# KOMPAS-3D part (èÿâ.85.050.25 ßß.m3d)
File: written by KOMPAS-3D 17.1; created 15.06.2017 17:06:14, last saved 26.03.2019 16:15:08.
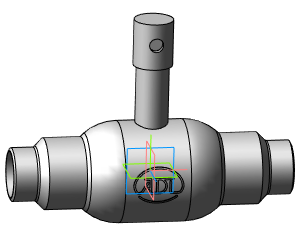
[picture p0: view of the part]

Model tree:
1. Операция без истории:2  (labels: Сталь 20  ГОСТ 1050-88)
